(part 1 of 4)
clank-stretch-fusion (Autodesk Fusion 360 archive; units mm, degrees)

design "AS_Clank-Stretch" references "FP_Cable-Tendie-Y", "AS_YRF", "AS_X-Beam", "AS_Stretch-Bed", "AS_Cable-Terminal-Y", "HW_M5x15-FHCS", "PP_EXTR_Bracket-HBLFSN5-SET", "AS_Rear-Stop", "AS_YLF"
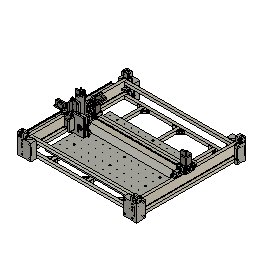
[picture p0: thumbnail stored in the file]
parameter "bed_x" = 620.5
parameter "bed_y" = 420
parameter "tcp_to_yl_rail_edge" = 75.7 (= "yl_rail_edge_to_flat + 62.7 mm")
parameter "tcp_to_yr_rail_edge" = 54.8 (= "yr_rail_edge_to_flat + 40.8 mm")
parameter "yl_rail_edge_to_flat" = 13
parameter "yr_rail_edge_to_flat" = 14
parameter "yl_yr_x_rail_insert" = 3
parameter "x_rail_edge_to_tcp" = 39
parameter "z_throw_down" = 22
parameter "z_rail_to_clearance" = 13.5
parameter "bed_mat_thickness" = 12.5
parameter "z_inter_frame" = 25
parameter "x_rail_edge_to_yl_yr_rear" = 80
parameter "d98" = 100
sketch "Sketch1" plane through (0, 0, 0) normal (0, 0, 1) x axis (1, 0, 0)
  line L1 (620.5, 0) -> (0, 0)
  line L2 (620.5, 420) -> (620.5, 0)
  line L3 (0, 420) -> (620.5, 420)
  line L4 (0, 0) -> (0, 420)
  line L5 (-95.7, -110) -> (-75.7, -110)
  line L6 (-95.7, 634) -> (-95.7, -110)
  line L7 (-75.7, 634) -> (-95.7, 634)
  line L8 (-75.7, -110) -> (-75.7, 634)
  line L9 (695.3, 634) -> (675.3, 634)
  line L10 (695.3, -110) -> (695.3, 634)
  line L11 (675.3, -110) -> (695.3, -110)
  line L12 (675.3, 634) -> (675.3, -110)
  line L13 (664.3, 59) -> (-65.7, 59)
  line L14 (664.3, 39) -> (664.3, 59)
  line L15 (-65.7, 39) -> (664.3, 39)
  line L16 (-65.7, 59) -> (-65.7, 39)
  line L17 (675.3, -80) -> (-75.7, -80)
  line L18 (-75.7, -60) -> (675.3, -60)
  line L19 (675.3, 604) -> (-75.7, 604)
  line L20 (675.3, 584) -> (-75.7, 584)
  line L21 (50.25, -60) -> (50.25, 584)
  line L22 (70.25, -60) -> (70.25, 584)
  line L23 (570.25, -60) -> (570.25, 584)
  line L24 (550.25, -60) -> (550.25, 584)
  line L25 (320.25, 584) -> (320.25, -60)
  line L26 (300.25, -60) -> (300.25, 584)
  point P1 (0, 0)
  point P2 (0, 0)
  point P6 (-75.7, -110)
  point P18 (-75.7, -80)
  point P19 (675.3, -80)
  point P20 (675.3, -60)
  point P21 (-75.7, -60)
  point P22 (-75.7, 604)
  point P23 (675.3, 604)
  point P24 (-75.7, 584)
  point P25 (675.3, 584)
  point P26 (50.25, 584)
  point P27 (50.25, -60)
  point P28 (70.25, 584)
  point P29 (70.25, -60)
  point P30 (570.25, 584)
  point P31 (570.25, -60)
  point P32 (550.25, 584)
  point P33 (550.25, -60)
  point P34 (320.25, -60)
  point P35 (320.25, 584)
  point P36 (300.25, 584)
  point P37 (300.25, -60)
  point P38 (310.25, 0)
  point P5 (0, 420)
  point P7 (-95.7, -110)
  point P17 (-65.7, 39)
  point P9 (-75.7, 634)
  point P3 (620.5, 0)
  point P16 (664.3, 39)
  horizontal L1
  vertical L2
  horizontal L3
  vertical L4
  coincident P1 P2
  horizontal L5
  vertical L6
  horizontal L7
  vertical L8
  horizontal L9
  vertical L10
  horizontal L11
  vertical L12
  equal L5 L11
  coincident P6 L11
  horizontal L13
  vertical L14
  horizontal L15
  vertical L16
  equal L5 L16
  equal L6 L10
  coincident L8 P18
  coincident L12 P19
  perpendicular L12 L17
  coincident L12 P20
  coincident L8 P21
  perpendicular L8 L18
  coincident L8 P22
  coincident L12 P23
  perpendicular L12 L19
  coincident L8 P24
  coincident L12 P25
  perpendicular L12 L20
  coincident L20 P26
  coincident L18 P27
  perpendicular L18 L21
  coincident L20 P28
  coincident L18 P29
  perpendicular L18 L22
  coincident L20 P30
  coincident L18 P31
  perpendicular L18 L23
  coincident L20 P32
  coincident L18 P33
  perpendicular L18 L24
  coincident L18 P34
  coincident L20 P35
  perpendicular L20 L25
  coincident L20 P36
  coincident L18 P37
  perpendicular L18 L26
  midpoint L1 P38
  dimension "d6" distance P2 P5 = 420 (= "bed_y")
  dimension "d7" distance P6 P7 = 20
  dimension "d8" distance L4 L8 = 75.7 (= "tcp_to_yl_rail_edge")
  dimension "d11" distance L2 L12 = 54.8 (= "tcp_to_yr_rail_edge")
  dimension "d12" distance L8 P17 = 10 (= "yl_rail_edge_to_flat - yl_yr_x_rail_insert")
  dimension "d16" distance L12 L14 = 11 (= "yr_rail_edge_to_flat - yl_yr_x_rail_insert")
  dimension "d17" distance P1 L15 = 39 (= "x_rail_edge_to_tcp")
  dimension "d64" distance P18 P21 = 20
  dimension "d65" distance P6 L17 = 30
  dimension "d66" distance P22 P24 = 20 (= "d64")
  dimension "d67" distance P9 L19 = 30
  dimension "d73" distance L4 L21 = 50.25
  dimension "d74" distance P27 P29 = 20
  dimension "d75" distance P3 L23 = 50.25 (= "d73")
  dimension "d76" distance P31 P33 = 20
  dimension "d77" distance L25 P38 = 10
  dimension "d78" distance L26 P38 = 10 (= "d77")
  dimension "d79" distance L1 L18 = 60
  dimension "d80" distance L13 L20 = 525 (= "bed_y + x_rail_edge_to_yl_yr_rear + 25 mm")
  dimension "d82" distance P16 P17 = 730
  dimension "d238" distance P2 P3 = 620.5 (= "bed_x")
  dimension "d244" distance L22 P34 = 250
  dimension "d265" distance L12 L23 = 105.05
  dimension "d266" distance L8 L21 = 125.95
extrude "Extrude1" new body sketch "Sketch1" profile of L5 L6 L7 L8 along normal blind 60 bodies "PP_EXTR_HFS5-2060-744"
extrude "Extrude4" new body sketch "Sketch1" profile of L5 L6 L7 L8 L18 L20 L21 L22 blind 20 from offset -45 (= "-z_inter_frame - 20 mm") bodies "PP_EXTR_HFS5-2020-744", "PP_EXTR_HFS5-2020-644"
extrude "Extrude6" sketch "Sketch1" profile of L8 L12 L17 L18 blind 20 bodies "PP_EXTR_HFS5-2020-751"
component_from_bodies "Body->Comp1"
component_from_bodies "Body->Comp2"
component_from_bodies "Body->Comp3"
component_from_bodies "Body->Comp4"
as_built_joint "As-built1"
as_built_joint "As-built2"
as_built_joint "As-built3"
as_built_joint "As-built4"
copy_paste "CopyPaste1"
joint "Assemble40" alignAngle 0 alignOffsetX 0 alignOffsetY -30 alignOffsetZ 0
copy_paste "CopyPaste2"
joint "Assemble41" alignAngle 0 alignOffsetX 0 alignOffsetY -30 alignOffsetZ 0
copy_paste "CopyPaste3"
joint "Assemble42" alignAngle 0 alignOffsetX 25 alignOffsetY 0 alignOffsetZ 0
copy_paste "CopyPaste4"
copy_paste "CopyPaste5"
joint "Assemble43" alignAngle 0 alignOffsetX 0 alignOffsetY 30 alignOffsetZ 0
joint "Assemble44" alignAngle 0 alignOffsetX 0 alignOffsetY -30 alignOffsetZ 0
copy_paste "CopyPaste6"
copy_paste "CopyPaste7"
joint "Assemble45" alignAngle 0 alignOffsetX 250 alignOffsetY 0 alignOffsetZ 0
joint "Assemble46" alignAngle 0 alignOffsetX 250 alignOffsetY 0 alignOffsetZ 0
component_insert "Component Insert1"
joint "Assemble47" alignAngle 0 alignOffsetX 28.5 alignOffsetY -7.35 alignOffsetZ 0 DistanceMinimum -565 (= "-100 mm - bed_y - 45 mm") DistanceMaximum -100 DistanceRest -300
component_insert "Component Insert42"
component_insert "Component Insert43"
joint "Assemble55" alignAngle 90 alignOffsetX 0 alignOffsetY 0 alignOffsetZ 0
joint "Assemble56" alignAngle 90 alignOffsetX 0 alignOffsetY 0 alignOffsetZ 0
component_insert "Component Insert33"
component_insert "Component Insert34"
component_insert "Component Insert35"
component_insert "Component Insert44"
joint "Assemble85" alignAngle -90 alignOffsetX 0 alignOffsetY 125 alignOffsetZ 0
joint "Assemble86" alignAngle 0 alignOffsetX 0 alignOffsetY 0 alignOffsetZ 0
joint "Assemble87" alignAngle 0 alignOffsetX 0 alignOffsetY 0 alignOffsetZ 0
joint "Assemble84" alignAngle -90 alignOffsetX 0 alignOffsetY 70 alignOffsetZ 0
component_insert "Component Insert47"
component_insert "Component Insert48"
component_insert "Component Insert49"
component_insert "Component Insert50"
component_insert "Component Insert51"
component_insert "Component Insert52"
joint "Assemble88" alignAngle -90 alignOffsetX 0 alignOffsetY 0 alignOffsetZ 0
joint "Assemble89" alignAngle -90 alignOffsetX 0 alignOffsetY 0 alignOffsetZ 0
joint "Assemble90" alignAngle -90 alignOffsetX 0 alignOffsetY 0 alignOffsetZ 0
joint "Assemble91" alignAngle -90 alignOffsetX 0 alignOffsetY 0 alignOffsetZ 0
joint "Assemble92" alignAngle 90 alignOffsetX 0 alignOffsetY 0 alignOffsetZ 0
joint "Assemble93" alignAngle 90 alignOffsetX 0 alignOffsetY 0 alignOffsetZ 0
component_insert "Component Insert36"
joint "Assemble54" alignAngle 0 alignOffsetX 0 alignOffsetY 0 alignOffsetZ 0
component_insert "Component Insert38"
joint "Assemble57" alignAngle 180 alignOffsetX 0 alignOffsetY 0 alignOffsetZ 0
component_insert "Component Insert45"
joint "Assemble58" alignAngle 0 alignOffsetX 0 alignOffsetY 0 alignOffsetZ 0
component_insert "Component Insert46"
joint "Assemble59" alignAngle 180 alignOffsetX 0 alignOffsetY 0 alignOffsetZ 0
component_insert "Component Insert41"
joint "Assemble60" alignAngle 0 alignOffsetX 0 alignOffsetY 60 alignOffsetZ 0
component_insert "Component Insert8"
joint "Assemble61" alignAngle 0 alignOffsetX 0 alignOffsetY 0 alignOffsetZ 0
component_insert "Component Insert9"
joint "Assemble62" alignAngle 180 alignOffsetX 0 alignOffsetY 0 alignOffsetZ 0
component_insert "Component Insert10"
joint "Assemble63" alignAngle 0 alignOffsetX 0 alignOffsetY 0 alignOffsetZ 0
component_insert "Component Insert11"
joint "Assemble64" alignAngle 180 alignOffsetX 0 alignOffsetY 0 alignOffsetZ 0
component_insert "Component Insert12"
joint "Assemble65" alignAngle 0 alignOffsetX 0 alignOffsetY 0 alignOffsetZ 0
component_insert "Component Insert13"
joint "Assemble66" alignAngle 0 alignOffsetX 0 alignOffsetY 0 alignOffsetZ 0
component_insert "Component Insert14"
joint "Assemble67" alignAngle 90 alignOffsetX 0 alignOffsetY 0 alignOffsetZ 0
component_insert "Component Insert15"
joint "Assemble68" alignAngle 90 alignOffsetX 0 alignOffsetY 0 alignOffsetZ 0
component_insert "Component Insert16"
component_insert "Component Insert17"
component_insert "Component Insert18"
component_insert "Component Insert19"
component_insert "Component Insert20"
component_insert "Component Insert21"
component_insert "Component Insert22"
component_insert "Component Insert23"
component_insert "Component Insert24"
component_insert "Component Insert25"
component_insert "Component Insert26"
component_insert "Component Insert27"
joint "Assemble69" alignAngle 270 alignOffsetX 0 alignOffsetY 0 alignOffsetZ 0
joint "Assemble70" alignAngle 0 alignOffsetX 0 alignOffsetY 0 alignOffsetZ 0
joint "Assemble71" alignAngle 270 alignOffsetX 0 alignOffsetY 0 alignOffsetZ 0
joint "Assemble72" alignAngle 180 alignOffsetX 0 alignOffsetY 0 alignOffsetZ 0
joint "Assemble73" alignAngle 270 alignOffsetX 0 alignOffsetY 0 alignOffsetZ 0
joint "Assemble74" alignAngle 180 alignOffsetX 0 alignOffsetY 0 alignOffsetZ 0
joint "Assemble75" alignAngle 90 alignOffsetX 0 alignOffsetY 0 alignOffsetZ 0
joint "Assemble76" alignAngle 180 alignOffsetX 0 alignOffsetY 0 alignOffsetZ 0
joint "Assemble77" alignAngle 90 alignOffsetX 0 alignOffsetY 0 alignOffsetZ 0
joint "Assemble78" alignAngle 0 alignOffsetX 0 alignOffsetY 0 alignOffsetZ 0
joint "Assemble79" alignAngle 90 alignOffsetX 0 alignOffsetY 0 alignOffsetZ 0
joint "Assemble80" alignAngle 0 alignOffsetX 0 alignOffsetY 0 alignOffsetZ 0
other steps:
base_feature "Base Feature1" bodies "PP_EXTR_HFS5-2020-644"
base_feature "Base Feature1" bodies "PP_EXTR_HFS5-2060-744"
base_feature "Base Feature1" bodies "PP_EXTR_HFS5-2020-744"
base_feature "Base Feature1" bodies "PP_EXTR_HFS5-2020-751"
create_component "CreateComponent1"
remove_body "RemoveBody1"
create_component "CreateComponent2"
remove_body "RemoveBody2"
create_component "CreateComponent3"
remove_body "RemoveBody3"
create_component "CreateComponent4"
remove_body "RemoveBody4"
joint_origin "JointOrigin1"
joint_origin "JointOrigin1"
joint_origin "JointOrigin2"
joint_origin "JointOrigin2"
joint_origin "JointOrigin1"
joint_origin "JointOrigin3"
joint_origin "JointOrigin3"
joint_origin "JointOrigin2"
joint_origin "JointOrigin4"
joint_origin "JointOrigin3"
joint_origin "JointOrigin1"
joint_origin "JointOrigin2"
joint_origin "JointOrigin3"
joint_origin "JointOrigin4"
joint_origin "JointOrigin6"
joint_origin "JointOrigin9"
joint_origin "JointOrigin7"
joint_origin "JointOrigin8"
joint_origin "JointOrigin12"
joint_origin "JointOrigin13"
joint_origin "JointOrigin14"
joint_origin "JointOrigin5"
joint_origin "JointOrigin9"
joint_origin "JointOrigin10"
joint_origin "JointOrigin11"
joint_origin "JointOrigin12"
joint_origin "JointOrigin13"
joint_origin "JointOrigin14"
joint_origin "JointOrigin15"
joint_origin "JointOrigin16"
joint_origin "JointOrigin6"
joint_origin "JointOrigin7"
joint_origin "JointOrigin8"
joint_origin "JointOrigin9"
joint_origin "JointOrigin10"
joint_origin "JointOrigin11"
joint_origin "JointOrigin13"
joint_origin "JointOrigin14"
joint_origin "JointOrigin15"
joint_origin "JointOrigin16"
joint_origin "JointOrigin17"
joint_origin "JointOrigin18"
joint_origin "JointOrigin17"
joint_origin "JointOrigin18"
named bodies: "PP_EXTR_HFS5-2060-744", "PP_EXTR_HFS5-2020-744", "PP_EXTR_HFS5-2020-751", "PP_EXTR_HFS5-2020-644"

design "AS_Grooved-Roller" references "HW_M4x16-BHCS", "PP_BRNG_4x13x6mm-VGroove", "HW_M4-Washer"
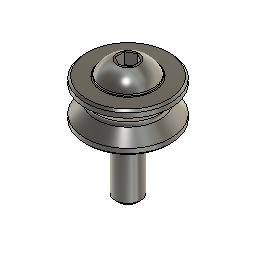
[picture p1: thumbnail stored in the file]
parameter "d27" = 0 comment "Bommer"
component_insert "Component Insert4"
ground "Ground2"
component_insert "Component Insert6"
joint "Assemble6" alignAngle 0 alignOffsetX 0 alignOffsetY 0 alignOffsetZ 0
component_insert "Component Insert7"
joint "Assemble7" alignAngle 0 alignOffsetX 0 alignOffsetY 0 alignOffsetZ 0

design "AS_Single-Roller" references "HW_M4x14-BHCS", "HW_M4-Washer", "PP_BRNG_624-4x13x5"
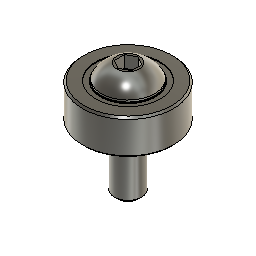
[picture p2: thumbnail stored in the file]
component_insert "Component Insert4" OffsetX 0 OffsetY 0 OffsetZ 0 AngleZ 0 alignAngle 0 alignOffsetX 0 alignOffsetY 0 alignOffsetZ 0
ground "Ground2"
component_insert "Component Insert5"
joint "Assemble3" alignAngle 0 alignOffsetX 0 alignOffsetY 0 alignOffsetZ 0
component_insert "Component Insert6"
joint "Assemble4" alignAngle 0 alignOffsetX 0 alignOffsetY 0 alignOffsetZ 0

design "PP_BRNG_624-4x13x5"
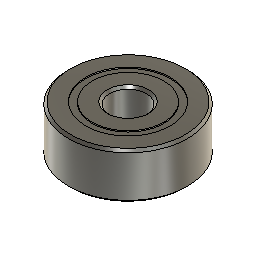
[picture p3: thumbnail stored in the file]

design "FP_Z-Drive"
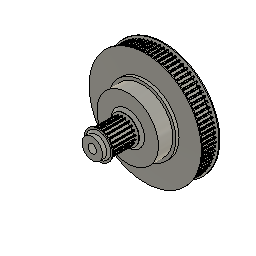
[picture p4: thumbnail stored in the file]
parameter "id_bearing" = 29.8
parameter "bearing_spread" = 20.5
sketch "Profile" plane through (0, 0, 0) normal (0, 0, 1) x axis (1, 0, 0)
  line L1 (0, 0) -> (0, 34.7)
  line L2 (6.3662, 3) -> (5, 3)
  line L3 (14.9, 24.2) -> (14.9, 17.2)
  line L4 (16.4, 24.2) -> (14.9, 24.2)
  line L5 (16.4, 25.7) -> (16.4, 24.2)
  line L6 (26.738, 25.7) -> (16.4, 25.7)
  line L7 (26.738, 34.7) -> (26.738, 25.7)
  line L8 (0, 34.7) -> (26.738, 34.7)
  line L9 (27.238, 34.2387) -> (25.238, 33.084)
  line L10 (27.238, 34.7) -> (27.238, 34.2387)
  line L11 (26.738, 34.7) -> (27.238, 34.7)
  line L12 (25.238, 34.7) -> (25.238, 33.084)
  line L13 (0, 30.2) -> (26.738, 30.2)
  line L14 (26.738, 25.7) -> (27.238, 25.7)
  line L15 (27.238, 25.7) -> (27.238, 26.1613)
  line L16 (27.238, 26.1613) -> (25.238, 27.316)
  line L17 (25.238, 25.7) -> (25.238, 27.316)
  line L18 (5, 0) -> (5, 3)
  line L19 (0, 0) -> (5, 0)
  line L20 (0, 2) -> (26.738, 2)
  line L21 (6.3662, 17.2) -> (14.9, 17.2)
  line L22 (6.3662, 3) -> (6.3662, 17.2)
  line L23 (14.9, 2) -> (14.9, 17.2)
  line L24 (0, 9.6) -> (14.9, 9.6)
  line L25 (2.075, 5) -> (2.075, 0)
  line L26 (2.25, 5.3031) -> (2.075, 5)
  line L27 (2.25, 34.7) -> (2.25, 5.3031)
  line L28 (6.3662, 14.6) -> (14.9, 14.6)
  line L29 (6.3662, 4.6) -> (14.9, 4.6)
  line L30 (4.8662, 14.6) -> (6.8662, 15.7547)
  line L31 (4.8662, 17.2) -> (4.8662, 14.6)
  line L32 (6.3662, 17.2) -> (4.8662, 17.2)
  line L33 (6.8662, 17.2) -> (6.8662, 15.7547)
  line L34 (6.8662, 3) -> (6.8662, 3.4453)
  line L35 (4.8662, 4.6) -> (6.8662, 3.4453)
  line L36 (4.8662, 3) -> (4.8662, 4.6)
  line L37 (6.8662, 3) -> (6.3662, 3)
  line L38 (4.8662, 3) -> (5, 3)
  point P2 (0, 34.7)
  point P9 (0, 34.7)
  point P1 (0, 0)
  point P8 (26.738, 34.7)
  point P13 (26.738, 34.7)
  point P14 (25.238, 34.7)
  point P15 (26.738, 30.2)
  point P16 (0, 30.2)
  point P17 (26.738, 33.95)
  point P10 (25.238, 33.084)
  point P21 (25.238, 27.316)
  point P11 (27.238, 34.2387)
  point P20 (27.238, 26.1613)
  point P12 (27.238, 34.7)
  point P18 (27.238, 25.7)
  point P19 (26.738, 25.7)
  point P22 (25.238, 25.7)
  point P3 (0, 0)
  point P25 (0, 0)
  point P27 (0, 2)
  point P26 (26.738, 2)
  point P31 (14.9, 2)
  point P32 (14.9, 9.6)
  point P33 (0, 9.6)
  point P34 (2.075, 0)
  point P37 (2.25, 34.7)
  point P38 (14.9, 14.6)
  point P39 (6.3662, 14.6)
  point P40 (14.9, 4.6)
  point P41 (6.3662, 4.6)
  point P45 (6.8662, 17.2)
  point P43 (4.8662, 14.6)
  point P42 (6.8662, 15.7547)
  point P46 (6.8662, 3.4453)
  point P47 (4.8662, 4.6)
  point P7 (26.738, 25.7)
  point P4 (14.9, 24.2)
  point P5 (16.4, 24.2)
  point P6 (16.4, 25.7)
  point P24 (5, 0)
  point P28 (14.9, 17.2)
  point P35 (2.075, 5)
  point P29 (6.3662, 17.2)
  point P44 (4.8662, 17.2)
  vertical L1
  perpendicular L1 L2
  perpendicular L3 L4
  perpendicular L4 L5
  perpendicular L5 L6
  perpendicular L6 L7
  perpendicular L7 L8
  coincident P2 P9
  coincident P1 L1
  parallel L7 L10
  perpendicular L10 L11
  coincident P8 P13
  coincident L8 P14
  perpendicular L8 L12
  midpoint L7 P15
  coincident L1 P16
  perpendicular L1 L13
  coincident L9 P17
  coincident L7 P17
  symmetric P10 L13 P21
  symmetric P11 L13 P20
  symmetric P12 L13 P18
  symmetric P13 L13 P19
  symmetric P14 L13 P22
  perpendicular L2 L18
  perpendicular L18 L19
  coincident P3 P25
  coincident P1 P25
  horizontal L8
  perpendicular L18 L20
  coincident L1 P27
  coincident L7 P26
  perpendicular L3 L21
  perpendicular L2 L22
  coincident L20 P31
  perpendicular L20 L23
  midpoint L23 P32
  coincident L1 P33
  perpendicular L1 L24
  coincident L19 P34
  perpendicular L20 L25
  coincident L8 P37
  perpendicular L8 L27
  coincident L23 P38
  coincident L22 P39
  perpendicular L22 L28
  coincident L23 P40
  coincident L22 P41
  perpendicular L22 L29
  perpendicular L28 L31
  perpendicular L31 L32
  coincident L21 P45
  perpendicular L21 L33
  coincident L28 P43
  symmetric L24 P42 P46
  symmetric L24 P43 P47
  perpendicular L34 L37
  perpendicular L36 L38
  vertical L36
  vertical L34
  dimension "d4" distance P1 L3 = 14.9 (= "id_bearing / 2")
  dimension "d5" distance P7 P8 = 9
  dimension "d6" distance P1 L7 = 26.738 (= "( nt_drive * 2 / PI / 2 ) * 1 mm")
  dimension "d7" distance P4 P5 = 1.5
  dimension "d8" distance P5 P6 = 1.5
  dimension "d30" distance P8 L10 = 0.5
  dimension "d31" distance L13 P17 = 3.75
  dimension "d32" angle L9 L10 = 60
  dimension "d33" distance P8 P14 = 1.5
  dimension "d75" distance P24 P25 = 5 (= "( 10 / 2 ) * 1 mm")
  dimension "d79" distance P24 L20 = 2
  dimension "d80" distance L2 L20 = 1
  dimension "d81" distance L20 L21 = 15.2
  dimension "d82" distance P4 P28 = 7
  dimension "d83" distance P1 L25 = 2.075 (= "( 4.15 / 2 ) * 1 mm")
  dimension "d84" angle L25 L26 = 30
  dimension "d86" distance P1 L27 = 2.25 (= "( 4.5 / 2 ) * 1 mm")
  dimension "d87" distance P34 P35 = 5
  dimension "d89" distance P1 L22 = 6.3662 (= "( nt_output * 2 / PI ) * 1 mm / 2")
  dimension "d109" distance P32 P38 = 5
  dimension "d110" distance P32 P40 = 5
  dimension "d111" distance P29 P45 = 0.5
  dimension "d113" angle L28 L30 = 30
  dimension "d114" distance P29 P44 = 1.5
revolve "Revolve1" sketch "Profile" AlongAngle 360 bodies "Z Drive Unit"
sketch "Tooth" plane through (0, 34.7, 0) normal (0, 1, 0) x axis (-1, 0, 0)
  line L1 (0, 26.738) -> (0, 0)
  line L2 (0, 0) -> (-0.9998, 26.7193)
  circle C1 centre (0, 0) radius 26.738
  circle C2 centre (0, 0) radius 25.612
  circle C3 centre (0, 0) radius 26.992
  circle C4 centre (0, 0) radius 26.362
  arc A1 centre (0, 26.162) radius 0.55 clockwise from (0, 25.612) to (-0.4889, 25.9101)
  arc A2 centre (-0.7379, 26.2016) radius 0.15 clockwise from (-0.7421, 26.3516) to (-0.5895, 26.2234)
  arc A3 centre (0.4, 26.3682) radius 1 clockwise from (-0.4889, 25.9101) to (-0.5895, 26.2234)
  circle C5 centre (0, 0) radius 2.25
  point P2 (0, 0)
  point P3 (0, 0)
  point P4 (0, 26.738)
  point P1 (0, 0)
  point P5 (0, 0)
  point P7 (0, 0)
  point P10 (0, 25.612)
  point P8 (0, 26.162)
  point P11 (-0.9998, 26.7193)
  point P12 (0, 0)
  point P13 (-0.7421, 26.3516)
  point P16 (0.4, 26.3682)
  coincident P2 P3
  coincident C1 P4
  vertical L1
  coincident P1 P5
  concentric C1 C3
  coincident P1 P7
  coincident C2 P10
  coincident L1 P10
  coincident L1 P8
  coincident C1 P11
  coincident P1 P12
  coincident C4 P13
  tangent C4 A2
  tangent A1 A3
  tangent A2 A3
  dimension "d14" distance C1 C3 = 0.254
  dimension "d15" distance C2 C3 = 1.38
  dimension "d16" distance C2 C4 = 0.75
  dimension "d17" radius A1 = 0.55
  dimension "d18" angle L1 L2 = 2.143 (= "( 180 / nt_drive ) * 1 deg")
  dimension "d19" radius A3 = 1
  dimension "d20" radius A2 = 0.15
  dimension "d21" distance L1 P16 = 0.4
extrude "Extrude1" new body sketch "Tooth" profile of C1 L1 C4 A1 L2 A2 A3 to an object
offset_faces "OffsetFaces1" distance 0.05
offset_faces "OffsetFaces2" distance -0.05
mirror "Mirror1" mirrorStitchTolerance 0.1
circular_pattern "C-Pattern1" TotalAngle 360
combine "Combine1"
revolve "Revolve2" sketch "Profile" AlongAngle 360
sketch "Sketch6" plane through (0, 3, 0) normal (0, -1, 0) x axis (1, 0, 0)
  line L1 (0, 6.3662) -> (0, 0)
  line L2 (-1.0356, 6.5387) -> (0, 0)
  circle C1 centre (0, 0) radius 6.3662
  circle C2 centre (0, 0) radius 5
  arc A1 centre (0, 5.7902) radius 0.55 clockwise from (0, 5.2402) to (-0.4889, 5.5382)
  arc A2 centre (0.4, 5.9964) radius 1 clockwise from (-0.4889, 5.5382) to (-0.5844, 5.8205)
  arc A3 centre (-0.7321, 5.7941) radius 0.15 clockwise from (-0.7509, 5.9429) to (-0.5844, 5.8205)
  circle C3 centre (0, 0) radius 6.6202
  circle C4 centre (0, 0) radius 5.2402
  circle C5 centre (0, 0) radius 5.9902
  point P2 (0, 0)
  point P3 (0, 0)
  point P4 (0, 6.3662)
  point P8 (0, 5.2402)
  point P9 (0, 5.7902)
  point P6 (-0.7509, 5.9429)
  point P14 (0, 0)
  point P15 (0, 0)
  point P16 (-1.0356, 6.5387)
  point P5 (0.4, 5.9964)
  coincident P2 P3
  coincident C1 P4
  vertical L1
  tangent A1 A2
  tangent A2 A3
  coincident L1 P8
  coincident L1 P9
  concentric C1 C3
  concentric C3 C4
  concentric C4 C5
  coincident P6 C5
  coincident P8 C4
  tangent A3 C5
  coincident P14 P15
  coincident C3 P16
  dimension "d90" radius A1 = 0.55
  dimension "d91" radius A2 = 1
  dimension "d92" radius A3 = 0.15
  dimension "d93" distance L1 P5 = 0.4
  dimension "d94" distance C1 C3 = 0.254
  dimension "d95" distance C3 C4 = 1.38
  dimension "d96" distance C4 C5 = 0.75
  dimension "d97" angle L1 L2 = 9 (= "( 180 / nt_output ) * 1 deg")
extrude "Extrude8" new body sketch "Sketch6" profile of C1 L1 A1 A2 A3 C5 L2 to an object
offset_faces "OffsetFaces3" distance 0.05
offset_faces "OffsetFaces4" distance -0.05
mirror "Mirror3" mirrorStitchTolerance 0.1
circular_pattern "C-Pattern3" TotalAngle 360
combine "Combine2"
revolve "Revolve3" sketch "Profile" AlongAngle 360
sketch "Sketch7" plane through (0, 34.7, 0) normal (0, 1, 0) x axis (-1, 0, 0)
  line L1 (-4.0415, 0) -> (-2.0207, 3.5)
  line L2 (-2.0207, -3.5) -> (-4.0415, 0)
  line L3 (2.0207, -3.5) -> (-2.0207, -3.5)
  line L4 (4.0415, 0) -> (2.0207, -3.5)
  line L5 (2.0207, 3.5) -> (4.0415, 0)
  line L6 (-2.0207, 3.5) -> (2.0207, 3.5)
  circle C1 centre (0, 0) radius 27.238
  circle C2 centre (0, 0) radius 2.25
  point P1 (0, 0)
  point P9 (0, 0)
  point P5 (-2.0207, -3.5)
  coincident P1 P9
  horizontal L6
  dimension "d116" distance P5 L6 = 7
extrude "Extrude9" cut sketch "Sketch7" profile of C2 L1 L2 L3 L4 L5 L6 to an object taper 1 from offset -7
chamfer "Chamfer3" distance 1.7
chamfer "Chamfer4" distance 1
sketch "Sketch8" plane through (0, 25.7, 0) normal (0, -1, 0) x axis (1, 0, 0)
  line L1 (0, 0) -> (0, 17.022)
  curve K1 (-0.5333, 25.8872) -> (0.5333, 25.8872)
  curve K2 (0.5333, 25.8872) -> (-0.5333, 25.8872)
  line L2 (0, 23.022) -> (0, 17.022)
  circle C1 centre (0, 0) radius 27.238
  circle C2 centre (0, 0) radius 16.4
  circle C3 centre (0, 17.022) radius 6
  point P3 (0, 17.022)
  point P4 (0, 17.022)
  point P2 (0, 0)
  point P5 (0, 0)
  point P8 (0, 17.022)
  point P9 (0, 23.022)
  point P10 (0, 11.022)
  point P11 (0, 23.022)
  point P12 (0, 25.562)
  coincident P3 P4
  coincident P2 P5
  vertical L1
  coincident P3 P8
  coincident C3 P9
  parallel L1 L2
  coincident C3 P10
  coincident L1 P10
  coincident P9 P11
  coincident K1 P12
  coincident K2 P12
  coincident L2 P12
  dimension "d121" diameter C3 = 12
  dimension "d122" distance P11 P12 = 2.54
extrude "Extrude10" cut sketch "Sketch8" profile of C2 C3 to an object from offset -2
chamfer "Chamfer5" distance 1
circular_pattern "C-Pattern5" TotalAngle 360
chamfer "Chamfer6" sketch "Tooth" distance 0.5
chamfer "Chamfer7" distance 1.25
named bodies: "Z Drive Unit"

design "HW_M3x14-FHCS"
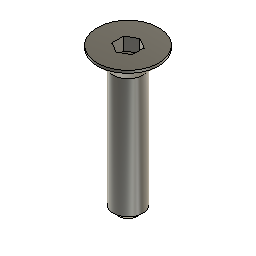
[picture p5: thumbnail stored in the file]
sketch "Sketch1" plane through (0, 0, 0) normal (0, 1, 0) x axis (1, 0, 0)
  line L1 (0, 14) -> (0, 0)
  line L2 (0.95, 14) -> (0, 14)
  line L3 (1.45, 13.5) -> (0.95, 14)
  line L4 (1.45, 1.8) -> (1.45, 13.5)
  line L5 (3, 0.25) -> (1.45, 1.8)
  line L6 (3, 0) -> (3, 0.25)
  line L7 (0, 0) -> (3, 0)
  point P1 (0, 0)
  point P2 (0, 0)
  point P9 (0, 0)
  point P3 (0, 14)
  point P4 (0.95, 14)
  point P8 (3, 0)
  point P7 (3, 0.25)
  coincident P1 P2
  vertical L1
  perpendicular L1 L2
  perpendicular L2 L4
  parallel L3 L5
  parallel L4 L6
  perpendicular L6 L7
  coincident P1 P9
  dimension "d1" distance P3 L4 = 1.45 (= "( 2.9 / 2 ) * 1 mm")
  dimension "d3" angle L2 L3 = 45
  dimension "d5" distance P4 L4 = 0.5
  dimension "d6" distance P2 P3 = 14
  dimension "d7" distance P8 P9 = 3 (= "( 6 / 2 ) * 1 mm")
  dimension "d9" distance P7 P8 = 0.25
revolve "Revolve1" sketch "Sketch1" AlongAngle 360
sketch "Sketch2" plane through (0, 0, 0) normal (0, 0, 1) x axis (-1, 0, 0)
  line L1 (0, -1.1547) -> (-1, -0.5774)
  line L2 (1, -0.5774) -> (0, -1.1547)
  line L3 (1, 0.5774) -> (1, -0.5774)
  line L4 (0, 1.1547) -> (1, 0.5774)
  line L5 (-1, 0.5774) -> (0, 1.1547)
  line L6 (-1, -0.5774) -> (-1, 0.5774)
  circle C1 centre (0, 0) radius 3
  point P1 (0, 0)
  point P9 (0, 0)
  coincident P1 P9
  vertical L6
  dimension "d12" distance L3 L6 = 2
extrude "Extrude1" cut sketch "Sketch2" profile of L1 L2 L3 L4 L5 L6 against normal blind 1.26

design "FP_HP-Pushrod"
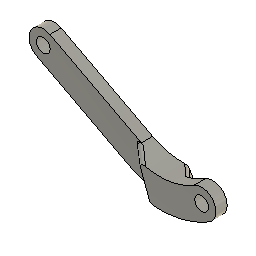
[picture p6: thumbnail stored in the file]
sketch "Sketch1" plane through (0, 0, 0) normal (0, 1, 0) x axis (1, 0, 0)
  line L1 (57.4992, 15.3) -> (0, 0)
  line L2 (43.3571, -7.7) -> (57.4992, 15.3)
  line L3 (43.3571, 19.3) -> (43.3571, -7.7)
  line L4 (30.7869, 16.1954) -> (0, 0)
  line L5 (-2.2347, 4.2481) -> (2.2347, -4.2481)
  line L6 (33.0216, 11.9473) -> (2.2347, -4.2481)
  line L7 (-2.2347, 4.2481) -> (28.5522, 20.4435)
  line L8 (33.0216, 11.9473) -> (28.5522, 20.4435)
  line L9 (35.4522, 23.1018) -> (30.8558, 10.808)
  line L10 (54.6732, 22.0184) -> (49.3571, 13.6738)
  circle C1 centre (0, 0) radius 1.625
  circle C2 centre (57.4992, 15.3) radius 1.625
  arc A1 centre (43.3571, -7.7) radius 27 clockwise from (43.3571, 19.3) to (57.4992, 15.3)
  arc A2 centre (43.3571, -7.7) radius 27 clockwise from (30.7869, 16.1954) to (43.3571, 19.3)
  arc A3 centre (43.3571, -7.7) radius 22.2 clockwise from (33.0216, 11.9473) to (54.9851, 11.2111)
  arc A4 centre (57.4992, 15.3) radius 4.8 clockwise from (60.0134, 19.3889) to (54.9851, 11.2111)
  arc A5 centre (43.3571, -7.7) radius 31.8 clockwise from (28.5522, 20.4435) to (60.0134, 19.3889)
  arc A6 centre (43.3571, -7.7) radius 27 clockwise from (30.7869, 16.1954) to (57.4992, 15.3)
  circle C3 centre (57.4992, 15.3) radius 2.3
  arc A7 centre (0, 0) radius 4.8 clockwise from (2.2347, -4.2481) to (-2.2347, 4.2481)
  circle C4 centre (0, 0) radius 2.3
  point P1 (0, 0)
  point P2 (0, 0)
  point P3 (57.4992, 15.3)
  point P5 (57.4992, 15.3)
  point P4 (0, 0)
  point P7 (57.4992, 15.3)
  point P9 (57.4992, 15.3)
  point P6 (43.3571, -7.7)
  point P10 (43.3571, -7.7)
  point P11 (43.3571, -7.7)
  point P19 (43.3571, -7.7)
  point P12 (30.7869, 16.1954)
  point P17 (30.7869, 16.1954)
  point P21 (0, 0)
  point P28 (54.6732, 22.0184)
  point P27 (49.3571, 13.6738)
  point P26 (35.4522, 23.1018)
  point P25 (30.8558, 10.808)
  point P8 (43.3571, 19.3)
  point P20 (57.4992, 15.3)
  point P24 (0, 0)
  point P16 (28.5522, 20.4435)
  coincident P1 P2
  equal C1 C2
  coincident P3 P5
  coincident P1 P4
  coincident P3 P7
  coincident P5 P9
  coincident P6 P10
  vertical L3
  coincident P6 P11
  tangent A2 L4
  tangent A3 A4
  tangent A4 A5
  coincident P6 P19
  coincident P12 P17
  concentric C2 C3
  coincident P1 P21
  coincident P2 L5
  perpendicular L4 L5
  equal A4 A7
  coincident P17 L8
  perpendicular L4 L8
  concentric C1 C4
  equal C3 C4
  coincident A5 P28
  coincident A3 P27
  coincident A5 P26
  coincident L6 P25
  dimension "d1" diameter C1 = 3.25
  dimension "d2" distance P4 P5 = 59.5 (= "56.5 mm + 3 mm")
  dimension "d6" distance P8 P10 = 27
  dimension "d7" = 31.6
  dimension "d8" diameter C3 = 4.6
  dimension "d9" distance A4 C3 = 2.5
  dimension "d10" distance P20 P24 = 15.3
  dimension "d19" distance P11 P20 = 23
  dimension "d29" angle L3 L10 = 32.5
  dimension "d30" distance L3 P27 = 6
  dimension "d38" distance P16 P26 = 6.9
  dimension "d40" angle L9 L10 = 12
extrude "Extrude4" new body sketch "Sketch1" profile of A3 A4 A5 C3 L9 L10 along normal blind 3.8 bodies "HP Pushrod"
extrude "Extrude5" new body sketch "Sketch1" profile of A3 A5 A7 L6 L7 C4 L9 L10 blind 3.8 from offset 4.2 (= "6.9 mm - 1.2 mm - 1.5 mm")
extrude "Extrude6" add sketch "Sketch1" profile of A3 A5 L6 L7 L9 L10 to an object
chamfer "Chamfer3" distance 4.2
chamfer "Chamfer4" distance 4.2
fillet "Fillet1" radius 1
named bodies: "HP Pushrod"

design "HW_M3x25-FHCS"
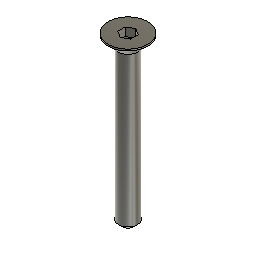
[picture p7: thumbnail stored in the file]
sketch "Sketch1" plane through (0, 0, 0) normal (0, 1, 0) x axis (1, 0, 0)
  line L1 (0, 25) -> (0, 0)
  line L2 (0.95, 25) -> (0, 25)
  line L3 (1.45, 24.5) -> (0.95, 25)
  line L4 (1.45, 1.8) -> (1.45, 24.5)
  line L5 (3, 0.25) -> (1.45, 1.8)
  line L6 (3, 0) -> (3, 0.25)
  line L7 (0, 0) -> (3, 0)
  point P1 (0, 0)
  point P2 (0, 0)
  point P9 (0, 0)
  point P3 (0, 25)
  point P4 (0.95, 25)
  point P8 (3, 0)
  point P7 (3, 0.25)
  coincident P1 P2
  vertical L1
  perpendicular L1 L2
  perpendicular L2 L4
  parallel L3 L5
  parallel L4 L6
  perpendicular L6 L7
  coincident P1 P9
  dimension "d1" distance P3 L4 = 1.45 (= "( 2.9 / 2 ) * 1 mm")
  dimension "d3" angle L2 L3 = 45
  dimension "d5" distance P4 L4 = 0.5
  dimension "d6" distance P2 P3 = 25
  dimension "d7" distance P8 P9 = 3 (= "( 6 / 2 ) * 1 mm")
  dimension "d9" distance P7 P8 = 0.25
revolve "Revolve1" sketch "Sketch1" AlongAngle 360
sketch "Sketch2" plane through (0, 0, 0) normal (0, 0, 1) x axis (-1, 0, 0)
  line L1 (0, -1.1547) -> (-1, -0.5774)
  line L2 (1, -0.5774) -> (0, -1.1547)
  line L3 (1, 0.5774) -> (1, -0.5774)
  line L4 (0, 1.1547) -> (1, 0.5774)
  line L5 (-1, 0.5774) -> (0, 1.1547)
  line L6 (-1, -0.5774) -> (-1, 0.5774)
  circle C1 centre (0, 0) radius 3
  point P1 (0, 0)
  point P9 (0, 0)
  coincident P1 P9
  vertical L6
  dimension "d12" distance L3 L6 = 2
extrude "Extrude1" cut sketch "Sketch2" profile of L1 L2 L3 L4 L5 L6 against normal blind 1.26

design "HW_M4x16-SHCS"
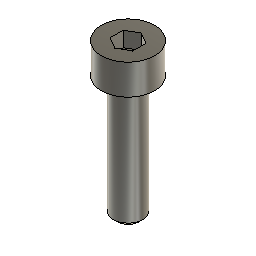
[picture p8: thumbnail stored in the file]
sketch "Sketch1" plane through (0, 0, 0) normal (0, 1, 0) x axis (1, 0, 0)
  line L1 (0, 16) -> (0, -4)
  line L2 (1.45, 16) -> (0, 16)
  line L3 (1.95, 15.5) -> (1.45, 16)
  line L4 (1.95, 0) -> (1.95, 15.5)
  line L5 (3.5, 0) -> (1.95, 0)
  line L6 (3.5, -4) -> (3.5, 0)
  line L7 (0, -4) -> (3.5, -4)
  point P1 (0, 0)
  point P4 (1.45, 16)
  point P5 (1.95, 15.5)
  point P3 (0, 16)
  point P7 (3.5, 0)
  point P8 (3.5, -4)
  point P2 (0, -4)
  vertical L1
  perpendicular L1 L2
  perpendicular L2 L4
  perpendicular L4 L5
  perpendicular L5 L6
  horizontal L7
  coincident P1 L1
  coincident P1 L5
  dimension "d1" distance P1 L2 = 16
  dimension "d2" angle L2 L3 = 45
  dimension "d3" distance P4 P5 = 0.5
  dimension "d4" distance P3 L4 = 1.95 (= "( 3.9 / 2 ) * 1 mm")
  dimension "d5" distance P7 P8 = 4
  dimension "d6" distance P2 P8 = 3.5 (= "( 7 / 2 ) * 1 mm")
revolve "Revolve1" sketch "Sketch1" AlongAngle 360
sketch "Sketch2" plane through (0, 0, 4) normal (0, 0, 1) x axis (-1, 0, 0)
  line L1 (0, -1.7321) -> (-1.5, -0.866)
  line L2 (1.5, -0.866) -> (0, -1.7321)
  line L3 (1.5, 0.866) -> (1.5, -0.866)
  line L4 (0, 1.7321) -> (1.5, 0.866)
  line L5 (-1.5, 0.866) -> (0, 1.7321)
  line L6 (-1.5, -0.866) -> (-1.5, 0.866)
  circle C1 centre (0, 0) radius 3.5
  point P1 (0, 0)
  point P9 (0, 0)
  point P5 (1.5, -0.866)
  coincident P1 P9
  vertical L6
  dimension "d8" distance P5 L6 = 3
extrude "Extrude1" cut sketch "Sketch2" profile of L1 L2 L3 L4 L5 L6 against normal blind 2

design "CT_Hotplate-Blade-Head" references "TE-10p-2p5-socket_1674231"
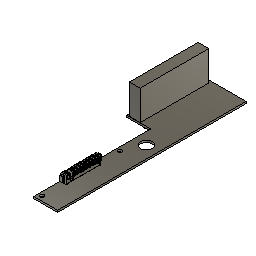
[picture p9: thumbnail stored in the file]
sketch "Sketch1" plane through (0, 0, 0) normal (0, 0, 1) x axis (1, 0, 0)
  line L1 (20, 0) -> (0, 0)
  line L2 (20, 73) -> (20, 0)
  line L3 (0, 73) -> (20, 73)
  line L4 (0, 0) -> (0, 73)
  line L5 (3, 4) -> (3, 69)
  line L6 (0, 36.5) -> (3, 36.5)
  line L7 (0, 69) -> (3, 69)
  line L8 (0, 98) -> (0, 73)
  line L9 (-20, 98) -> (0, 98)
  line L10 (-20, 158) -> (-20, 98)
  line L11 (20, 158) -> (-20, 158)
  line L12 (20, 73) -> (20, 158)
  line L13 (-9, 155.75) -> (-18, 155.75)
  line L14 (-9, 98.25) -> (-9, 155.75)
  line L15 (-18, 98.25) -> (-9, 98.25)
  line L16 (-18, 155.75) -> (-18, 98.25)
  line L17 (-11, 146) -> (-16, 146)
  line L18 (-11, 108) -> (-11, 146)
  line L19 (-16, 108) -> (-11, 108)
  line L20 (-16, 146) -> (-16, 108)
  line L21 (-9, 98.25) -> (-18, 155.75)
  line L22 (-11, 146) -> (-16, 108)
  line L23 (-1, 155) -> (-1, 158)
  line L24 (5, 155) -> (-1, 155)
  line L25 (5, 158) -> (5, 155)
  line L26 (11, 155) -> (11, 158)
  line L27 (17, 155) -> (11, 155)
  line L28 (17, 158) -> (17, 155)
  line L29 (-8.5, 102) -> (-8.5, 152)
  circle C1 centre (3, 4) radius 1.625
  circle C2 centre (3, 69) radius 1.625
  circle C3 centre (3, 69) radius 3
  circle C4 centre (10, 84.5) radius 5
  circle C5 centre (-8.5, 102) radius 1.5
  circle C6 centre (-7, 132) radius 1.5
  circle C7 centre (-8.5, 152) radius 1.5
  point P1 (0, 0)
  point P2 (0, 0)
  point P7 (3, 4)
  point P8 (3, 4)
  point P6 (3, 69)
  point P9 (3, 69)
  point P10 (3, 36.5)
  point P11 (0, 36.5)
  point P12 (3, 69)
  point P13 (0, 69)
  point P14 (1.375, 69)
  point P4 (20, 73)
  point P20 (20, 73)
  point P33 (5, 158)
  point P30 (-1, 158)
  point P34 (11, 158)
  point P37 (17, 158)
  point P32 (5, 155)
  point P38 (2, 155)
  point P39 (14, 155)
  point P40 (-13.5, 127)
  point P43 (-8.5, 152)
  point P44 (-8.5, 152)
  point P41 (-8.5, 102)
  point P45 (-8.5, 102)
  point P5 (0, 73)
  point P16 (0, 98)
  point P3 (20, 0)
  point P17 (-20, 98)
  point P18 (-20, 158)
  point P21 (-18, 155.75)
  point P22 (-9, 155.75)
  point P15 (3, 69)
  point P25 (10, 84.5)
  point P26 (-16, 146)
  point P27 (-11, 146)
  point P29 (-16, 108)
  point P23 (-9, 98.25)
  point P31 (-1, 155)
  point P42 (-7, 132)
  horizontal L1
  vertical L2
  horizontal L3
  vertical L4
  coincident P1 P2
  vertical L5
  coincident P7 P8
  coincident P6 P9
  equal C1 C2
  midpoint L5 P10
  midpoint L4 P11
  horizontal L6
  coincident P9 P12
  coincident L4 P13
  perpendicular L4 L7
  coincident C2 P14
  coincident L7 P14
  concentric C2 C3
  perpendicular L3 L8
  perpendicular L8 L9
  perpendicular L9 L10
  perpendicular L10 L11
  perpendicular L3 L12
  coincident P4 P20
  horizontal L13
  vertical L14
  horizontal L15
  vertical L16
  horizontal L17
  vertical L18
  horizontal L19
  vertical L20
  midpoint L21 L22
  vertical L23
  perpendicular L23 L24
  perpendicular L24 L25
  vertical L26
  perpendicular L26 L27
  perpendicular L27 L28
  coincident L11 P33
  coincident L11 P30
  coincident L11 P34
  coincident L11 P37
  coincident P32 L27
  equal L24 L27
  midpoint L24 P38
  midpoint L27 P39
  midpoint L21 P40
  coincident P43 P44
  coincident P41 P45
  vertical L29
  equal C6 C7
  equal C5 C7
  dimension "d1" distance P2 P5 = 73
  dimension "d2" diameter C2 = 3.25
  dimension "d3" distance P6 P7 = 65
  dimension "d4" distance P10 P11 = 3
  dimension "d5" distance L4 P14 = 1.375
  dimension "d6" diameter C3 = 6
  dimension "d13" distance P5 P16 = 25 (= "23.5 mm + 1.5 mm")
  dimension "d14" distance P2 P3 = 20
  dimension "d15" distance P17 P18 = 60
  dimension "d16" distance P16 P17 = 20
  dimension "d18" distance P21 P22 = 9
  dimension "d20" distance P17 L15 = 0.25
  dimension "d21" diameter C4 = 10
  dimension "d22" distance P15 P25 = 15.5
  dimension "d23" distance P15 P25 = 7
  dimension "d24" distance P26 P27 = 5
  dimension "d25" distance P26 P29 = 38
  dimension "d30" distance P22 P23 = 57.5
  dimension "d31" distance P31 P32 = 6
  dimension "d32" distance P38 P39 = 12
  dimension "d33" distance L10 P40 = 6.5
  dimension "d34" distance P38 P40 = 15.5
  dimension "d35" distance P30 P31 = 3
  dimension "d36" diameter C7 = 3
  dimension "d37" distance P17 L29 = 11.5
  dimension "d38" distance L9 P41 = 4
  dimension "d39" distance L11 P43 = 6
  dimension "d40" distance L10 P42 = 13
  dimension "d41" distance L9 P42 = 34
extrude "Extrude1" new body sketch "Sketch1" profile of L1 L2 L4 C1 C2 L8 L9 L10 L11 L12 L13 L14 L15 L16 C4 L17 L18 L19 L20 against normal blind 1.6
extrude "Extrude2" add sketch "Sketch1" profile of L13 L14 L15 L16 L17 L18 L19 L20 along normal blind 25
extrude "Extrude3" add sketch "Sketch1" profile of L17 L18 L19 L20 against normal blind 4.5
component_insert "Component Insert" sketch "Sketch1"
joint "Assemble1" sketch "Sketch1" alignAngle 90 alignOffsetX 0 alignOffsetY 0 alignOffsetZ 0.7
extrude "Extrude4" sketch "Sketch1" profile of L11 L23 L24 L25 L26 L27 L28 blind -3
extrude "Extrude5" sketch "Sketch1" profile of L14 C5 C6 C7 blind -3
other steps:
joint_origin "JointOrigin2" sketch "Sketch1"

design "PP_TRNS_Servo-Arm"
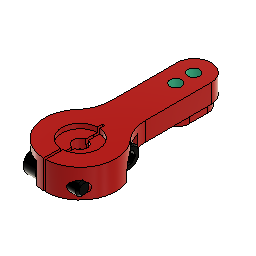
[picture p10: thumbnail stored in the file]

design "AS_XZ-Interposer" references "HW_M4x14-BHCS", "HW_M4-Nylock", "AS_Hotplate-Toolchanger", "HW_M4x10-BHCS", "HW_M4x14-FHCS", "HW_M4x25-SHCS", "HW_M4x20-FHCS", "PP_SHFT_6x200"
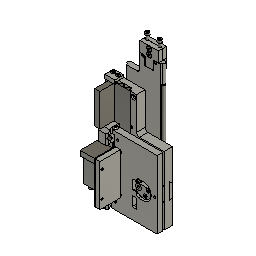
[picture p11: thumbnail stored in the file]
sketch "Plan" plane through (0, 0, 0) normal (0, 0, 1) x axis (1, 0, 0)
  line L1 (0, 0) -> (-29.8824, 0)
  line L2 (0, 9) -> (0, 0)
  line L3 (-29.8824, 9) -> (0, 9)
  line L4 (-29.8824, 0) -> (-29.8824, 9)
  line L5 (-26.2648, 5.75) -> (-33, 5.75)
  line L6 (0, 5.75) -> (-26.2648, 5.75)
  line L7 (-32, 8.75) -> (-45, 8.75)
  line L8 (-32, 2.75) -> (-32, 8.75)
  line L9 (-45, 2.75) -> (-32, 2.75)
  line L10 (-45, 8.75) -> (-45, 2.75)
  line L11 (-38.5, 2.75) -> (-38.5, 8.75)
  line L12 (-34.375, 5.75) -> (-32, 8.125)
  line L13 (-32, 3.375) -> (-34.375, 5.75)
  circle C1 centre (-30.1324, 5.75) radius 3
  point P13 (-32, 5.75)
  point P14 (-38.5, 8.75)
  point P15 (-38.5, 2.75)
  point P1 (0, 0)
  point P3 (0, 0)
  point P8 (0, 5.75)
  point P16 (-30.1324, 5.75)
  point P17 (-32, 8.125)
  point P19 (-32, 3.375)
  point P18 (-34.375, 5.75)
  point P9 (-45, 8.75)
  point P10 (-32, 8.75)
  point P12 (-45, 2.75)
  point P7 (-33, 5.75)
  horizontal L1
  vertical L2
  horizontal L3
  vertical L4
  horizontal L5
  perpendicular L4 L6
  horizontal L7
  vertical L8
  horizontal L9
  vertical L10
  midpoint L8 P13
  coincident L5 P13
  midpoint L7 P14
  midpoint L9 P15
  coincident P1 P3
  coincident L2 P8
  coincident L5 P16
  coincident L8 P17
  coincident L8 P19
  coincident L5 P18
  tangent C1 L12
  dimension "d2" distance P1 P8 = 5.75
  dimension "d4" distance P9 P10 = 13
  dimension "d5" distance P9 P12 = 6
  dimension "d6" distance P7 P13 = 1
  dimension "d7" distance P1 L11 = 38.5
  dimension "d77" diameter C1 = 6
  dimension "d78" angle L8 L13 = 45
  dimension "d79" angle L8 L12 = 45 (= "d78")
  dimension "d80" distance P17 P19 = 4.75
  dimension "d81" distance L4 P16 = 0.25
  dimension "d405" distance L3 P10 = 0.25
extrude "Extrude1" new body sketch "Plan" profile of L1 L2 L3 L4 C1 along normal blind 200
extrude "Extrude9" add sketch "Plan" profile of L1 L2 L3 L4 C1 against normal blind 2.17 (magnitude of "-1.67 mm - 0.5 mm")
extrude "Extrude10" sketch "Plan" profile of L1 L2 L3 L4 C1 blind 2.17 (= "1.67 mm + 0.5 mm")
offset_faces "OffsetFaces1" distance -0.5
fillet "Fillet4" radius 2
mirror "Mirror1" mirrorStitchTolerance 0.1
sketch "Mounts" plane through (0, 0, 0) normal (0, 1, 0) x axis (1, 0, 0)
  line L1 (0, -5.83) -> (0, 0)
  line L2 (23, -5.83) -> (-15, -5.83)
  line L3 (23, -83.7885) -> (26.5, -85.8093)
  line L4 (19.5, -85.8093) -> (23, -83.7885)
  line L5 (19.5, -89.8507) -> (19.5, -85.8093)
  line L6 (23, -91.8715) -> (19.5, -89.8507)
  line L7 (26.5, -89.8507) -> (23, -91.8715)
  line L8 (26.5, -85.8093) -> (26.5, -89.8507)
  line L9 (-10, -108.8715) -> (-13.5, -106.8507)
  line L10 (-6.5, -106.8507) -> (-10, -108.8715)
  line L11 (-6.5, -102.8093) -> (-6.5, -106.8507)
  line L12 (-10, -100.7885) -> (-6.5, -102.8093)
  line L13 (-13.5, -102.8093) -> (-10, -100.7885)
  line L14 (-13.5, -106.8507) -> (-13.5, -102.8093)
  line L15 (-5, -63.8715) -> (-8.5, -61.8507)
  line L16 (-1.5, -61.8507) -> (-5, -63.8715)
  line L17 (-1.5, -57.8093) -> (-1.5, -61.8507)
  line L18 (-5, -55.7885) -> (-1.5, -57.8093)
  line L19 (-8.5, -57.8093) -> (-5, -55.7885)
  line L20 (-8.5, -61.8507) -> (-8.5, -57.8093)
  line L21 (-15, -9.8715) -> (-18.5, -7.8507)
  line L22 (-11.5, -7.8507) -> (-15, -9.8715)
  line L23 (-11.5, -3.8093) -> (-11.5, -7.8507)
  line L24 (-15, -1.7885) -> (-11.5, -3.8093)
  line L25 (-18.5, -3.8093) -> (-15, -1.7885)
  line L26 (-18.5, -7.8507) -> (-18.5, -3.8093)
  line L27 (23, -9.8715) -> (19.5, -7.8507)
  line L28 (26.5, -7.8507) -> (23, -9.8715)
  line L29 (26.5, -3.8093) -> (26.5, -7.8507)
  line L30 (23, -1.7885) -> (26.5, -3.8093)
  line L31 (19.5, -3.8093) -> (23, -1.7885)
  line L32 (19.5, -7.8507) -> (19.5, -3.8093)
  line L33 (29.8824, 2.17) -> (-29.8824, 2.17)
  line L34 (29.8824, -202.17) -> (-29.8824, -202.17)
  line L35 (10.45, -202.17) -> (10.45, 2.17)
  line L36 (17.7, -202.17) -> (17.7, 2.17)
  line L37 (3.2, 2.17) -> (3.2, -202.17)
  line L38 (-11, -87.83) -> (23, -87.83)
  line L39 (-14.5, -89.8507) -> (-14.5, -85.8093)
  line L40 (-11, -83.7885) -> (-7.5, -85.8093)
  line L41 (-14.5, -85.8093) -> (-11, -83.7885)
  line L42 (-7.5, -85.8093) -> (-7.5, -89.8507)
  line L43 (-7.5, -89.8507) -> (-11, -91.8715)
  line L44 (-11, -91.8715) -> (-14.5, -89.8507)
  line L45 (-2, -177.8715) -> (-5.5, -175.8507)
  line L46 (-2, -169.7885) -> (1.5, -171.8093)
  line L47 (-5.5, -171.8093) -> (-2, -169.7885)
  line L48 (1.5, -171.8093) -> (1.5, -175.8507)
  line L49 (-5.5, -175.8507) -> (-5.5, -171.8093)
  line L50 (1.5, -175.8507) -> (-2, -177.8715)
  circle C1 centre (-5, -59.83) radius 2.125
  circle C2 centre (-15, -5.83) radius 2.125
  circle C3 centre (23, -5.83) radius 2.125
  circle C4 centre (-10, -104.83) radius 2.125
  circle C5 centre (23, -87.83) radius 2.125
  circle C6 centre (-11, -87.83) radius 2.125
  circle C7 centre (-2, -173.83) radius 2.125
  point P1 (0, 0)
  point P3 (0, 0)
  point P5 (-15, -5.83)
  point P8 (-15, -5.83)
  point P6 (23, -5.83)
  point P9 (23, -5.83)
  point P11 (23, -87.83)
  point P18 (23, -87.83)
  point P10 (-10, -104.83)
  point P25 (-10, -104.83)
  point P7 (-5, -59.83)
  point P32 (-5, -59.83)
  point P39 (-15, -5.83)
  point P46 (23, -5.83)
  point P52 (10.45, 2.17)
  point P53 (10.45, -202.17)
  point P54 (17.7, 2.17)
  point P55 (17.7, -202.17)
  point P56 (3.2, -202.17)
  point P57 (3.2, 2.17)
  point P58 (0, 2.17)
  point P59 (23, -87.83)
  point P63 (-11, -87.83)
  point P68 (-11, -87.83)
  point P69 (-11, -87.83)
  point P60 (-11, -87.83)
  point P71 (-2, -173.83)
  point P77 (-2, -173.83)
  point P14 (19.5, -85.8093)
  point P4 (0, -5.83)
  point P62 (-14.5, -85.8093)
  horizontal L2
  coincident P1 P3
  coincident P5 P8
  coincident P6 P9
  equal C1 C2
  equal C2 C3
  equal C2 C4
  equal C2 C5
  coincident P11 P18
  vertical L5
  vertical L14
  vertical L20
  vertical L26
  vertical L32
  equal L8 L11
  equal L17 L23
  equal L23 L29
  equal L8 L29
  coincident P10 P25
  coincident P7 P32
  coincident P8 P39
  coincident P9 P46
  vertical L1
  coincident L33 P52
  coincident L34 P53
  perpendicular L34 L35
  coincident L33 P54
  coincident L34 P55
  perpendicular L34 L36
  coincident L34 P56
  coincident L33 P57
  perpendicular L33 L37
  midpoint L33 P58
  coincident P11 P59
  perpendicular L37 L38
  coincident P63 P68
  vertical L39
  coincident P63 P69
  coincident P60 P69
  equal C4 C6
  vertical L49
  coincident P71 P77
  equal L11 L48
  equal C4 C7
  dimension "d45" distance P1 P7 = 5
  dimension "d47" diameter C2 = 4.25
  dimension "d51" distance P14 L8 = 7
  dimension "d93" distance P1 P52 = 10.45
  dimension "d94" distance P52 P57 = 7.25 (= "( 14.5 / 2 ) * 1 mm")
  dimension "d95" distance P52 P54 = 7.25 (= "d94")
  dimension "d135" distance P1 P25 = 10
  dimension "d136" distance L2 L33 = 8
  dimension "d137" distance P10 L33 = 107
  dimension "d138" distance P11 P58 = 23
  dimension "d139" distance P18 L33 = 90
  dimension "d144" distance P4 P39 = 15
  dimension "d145" distance P4 P9 = 23
  dimension "d146" distance P32 L33 = 62
  dimension "d147" distance P62 L42 = 7
  dimension "d148" distance P58 P63 = 11
  dimension "d415" distance P10 P71 = 8
  dimension "d416" distance P10 P77 = 69
extrude "Extrude3" cut sketch "Mounts" profile of C1 C2 C3 C4 C5 C6 C7 to an object
extrude "Extrude7" cut sketch "Mounts" profile of C1 C2 C3 C4 C5 L3 L4 L5 L6 L7 L8 L9 L10 L11 L12 L13 L14 L15 L16 L17 L18 L19 L20 L21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 to an object from offset 2
extrude "Extrude11" sketch "Mounts" profile of C3 L33 L4 L5 L6 L27 L28 L30 L31 L32 L34 L36 L37 blind -2.5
